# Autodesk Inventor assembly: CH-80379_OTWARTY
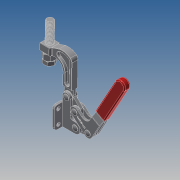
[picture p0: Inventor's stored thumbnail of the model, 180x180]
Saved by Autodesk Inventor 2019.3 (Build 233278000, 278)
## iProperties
Company: Î¢ÈíÖÐ¹ú
Created: 2012-10
Part Number: CH-80379_OTWARTY
Material: Ogólny
Description: STEP AP203
Document SubType Name: Assembly
Designer: CADENGINEERING4
Sending System: SolidWorks 2010
Preprocessor: SwSTEP 2.0
Title: CH-80379.STEP
Author: Î¢ÈíÓÃ»§
Revision Number: ÈÎºÎ
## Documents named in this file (9)
- E:\SERWER_ZAPAS\F clamp\CH-80379\CH-80379_OTWARTY.iam
- E:\SERWER_ZAPAS\F clamp\CH-80379\1-2-12X2 1-2.ipt
- E:\SERWER_ZAPAS\F clamp\CH-80379\80379-04 CONNECTING-PLATE.ipt
- E:\SERWER_ZAPAS\F clamp\CH-80379\80379-06_Default.ipt
- E:\SERWER_ZAPAS\F clamp\CH-80379\80379-03 HANDLE.ipt
- E:\SERWER_ZAPAS\F clamp\CH-80379\1-2 NUT.ipt
- E:\SERWER_ZAPAS\F clamp\CH-80379\80379-01 FLANGED BASE.ipt
- E:\SERWER_ZAPAS\F clamp\CH-80379\80379-02 BAR.ipt
- E:\SERWER_ZAPAS\F clamp\CH-80379\80325-05.ipt
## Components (12 placed, 12 different names)
1. 1-2-12X2 1-2_1 — Zestawiające:1, Zestawiające:2, Zestawiające:4
2. 80379-04 CONNECTING-PLATE_2 — Zestawiające:8, Zestawiające:9, Zestawiające:10
3. 80379-06_Default_3 — Zestawiające:17, Zestawiające:18
4. 80379-03 HANDLE_4 — Zestawiające:5, Zestawiające:6, Zestawiające:7, Zestawiające:13, Zestawiające:14, Zestawiające:15, Zestawiające:16, Zestawiające:23, Zestawiające:24, Zestawiające:25, Przejściowe:1
5. 80379-06_Default_5 — Zestawiające:15, Zestawiające:16
6. 1-2 NUT_6 — Zestawiające:2, Zestawiające:3, Zestawiające:4
7. 80379-01 FLANGED BASE_7 — Zestawiające:11, Zestawiające:12, Zestawiające:17, Zestawiające:18, Zestawiające:19, Zestawiające:20, Zestawiające:21, Zestawiające:22, Przejściowe:1
8. 80379-02 BAR_8 — Zestawiające:1, Zestawiające:3, Zestawiające:19, Zestawiające:20, Zestawiające:23
9. 80379-04 CONNECTING-PLATE_9 — Zestawiające:8, Zestawiające:9, Zestawiające:10, Zestawiające:11, Zestawiające:12, Zestawiające:13, Zestawiające:14
10. 80379-06_Default_10 — Zestawiające:24, Zestawiające:25
11. 80379-06_Default_11 — Zestawiające:21, Zestawiające:22
12. 80325-05_12 — Zestawiające:5, Zestawiające:6, Zestawiające:7
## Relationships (26: Mate 25, Transitional 1)
- Zestawiające:1 [Mate]: 1-2-12X2 1-2_1 ↔ 80379-02 BAR_8
- Zestawiające:2 [Mate]: 1-2-12X2 1-2_1 ↔ 1-2 NUT_6
- Zestawiające:3 [Mate]: 1-2 NUT_6 ↔ 80379-02 BAR_8
- Zestawiające:4 [Mate]: 1-2-12X2 1-2_1 ↔ 1-2 NUT_6
- Zestawiające:5 [Mate]: 80379-03 HANDLE_4 ↔ 80325-05_12
- Zestawiające:6 [Mate]: 80379-03 HANDLE_4 ↔ 80325-05_12
- Zestawiające:7 [Mate]: 80379-03 HANDLE_4 ↔ 80325-05_12
- Zestawiające:8 [Mate]: 80379-04 CONNECTING-PLATE_2 ↔ 80379-04 CONNECTING-PLATE_9
- Zestawiające:9 [Mate]: 80379-04 CONNECTING-PLATE_2 ↔ 80379-04 CONNECTING-PLATE_9
- Zestawiające:10 [Mate]: 80379-04 CONNECTING-PLATE_2 ↔ 80379-04 CONNECTING-PLATE_9
- Zestawiające:11 [Mate]: 80379-01 FLANGED BASE_7 ↔ 80379-04 CONNECTING-PLATE_9
- Zestawiające:12 [Mate]: 80379-01 FLANGED BASE_7 ↔ 80379-04 CONNECTING-PLATE_9
- Zestawiające:13 [Mate]: 80379-03 HANDLE_4 ↔ 80379-04 CONNECTING-PLATE_9
- Zestawiające:14 [Mate]: 80379-03 HANDLE_4 ↔ 80379-04 CONNECTING-PLATE_9
- Zestawiające:15 [Mate]: 80379-03 HANDLE_4 ↔ 80379-06_Default_5
- Zestawiające:16 [Mate]: 80379-03 HANDLE_4 ↔ 80379-06_Default_5
- Zestawiające:17 [Mate]: 80379-06_Default_3 ↔ 80379-01 FLANGED BASE_7
- Zestawiające:18 [Mate]: 80379-06_Default_3 ↔ 80379-01 FLANGED BASE_7
- Zestawiające:19 [Mate]: 80379-01 FLANGED BASE_7 ↔ 80379-02 BAR_8
- Zestawiające:20 [Mate]: 80379-01 FLANGED BASE_7 ↔ 80379-02 BAR_8
- Zestawiające:21 [Mate]: 80379-01 FLANGED BASE_7 ↔ 80379-06_Default_11
- Zestawiające:22 [Mate]: 80379-01 FLANGED BASE_7 ↔ 80379-06_Default_11
- Zestawiające:23 [Mate]: 80379-03 HANDLE_4 ↔ 80379-02 BAR_8
- Zestawiające:24 [Mate]: 80379-03 HANDLE_4 ↔ 80379-06_Default_10
- Zestawiające:25 [Mate]: 80379-03 HANDLE_4 ↔ 80379-06_Default_10
- Przejściowe:1 [Transitional]: 80379-03 HANDLE_4 ↔ 80379-01 FLANGED BASE_7
